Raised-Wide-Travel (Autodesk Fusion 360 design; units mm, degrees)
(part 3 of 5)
sketch "Support-free horizontal rail hole roof" plane through (0, 0, 54.9) normal (0, 0, 1) x axis (1, 0, 0)
  line L1 (-28.0908, -83.0908) -> (-28.0908, -86.9092)
  line L2 (-26.1816, -85) -> (-28.0908, -83.0908)
  line L3 (-28.0908, -86.9092) -> (-26.1816, -85)
extrude "Extrude66" cut sketch "Support-free horizontal rail hole roof" along normal blind 9.2
work_plane "WorkPlane67" AlongDistance 54.9 ExtraOffset 0
sketch "Support-free horizontal rail hole roof (1)" plane through (0, 0, 54.9) normal (0, 0, 1) x axis (1, 0, 0)
  line L1 (-28.0908, 86.9092) -> (-28.0908, 83.0908)
  line L2 (-26.1816, 85) -> (-28.0908, 86.9092)
  line L3 (-28.0908, 83.0908) -> (-26.1816, 85)
extrude "Extrude67" cut sketch "Support-free horizontal rail hole roof (1)" along normal blind 9.2
work_plane "WorkPlane61" AlongDistance 54.9 ExtraOffset 0
sketch "Support-free horizontal rail hole roof" plane through (0, 0, 54.9) normal (0, 0, 1) x axis (1, 0, 0)
  line L1 (31.9092, -83.0908) -> (31.9092, -86.9092)
  line L2 (33.8184, -85) -> (31.9092, -83.0908)
  line L3 (31.9092, -86.9092) -> (33.8184, -85)
extrude "Extrude61" cut sketch "Support-free horizontal rail hole roof" along normal blind 9.2
work_plane "WorkPlane62" AlongDistance 54.9 ExtraOffset 0
sketch "Support-free horizontal rail hole roof (1)" plane through (0, 0, 54.9) normal (0, 0, 1) x axis (1, 0, 0)
  line L1 (31.9092, 86.9092) -> (31.9092, 83.0908)
  line L2 (33.8184, 85) -> (31.9092, 86.9092)
  line L3 (31.9092, 83.0908) -> (33.8184, 85)
extrude "Extrude62" cut sketch "Support-free horizontal rail hole roof (1)" along normal blind 9.2
work_plane "WorkPlane14" AlongDistance 4 ExtraOffset 0
sketch "Reinforced roof over support-free pivot bore" plane through (4, 0, 0) normal (1, 0, 0) x axis (0, 0, -1)
  line L1 (-17.9, -29) -> (-17.9, -41)
  line L2 (-20, -29) -> (-17.9, -29)
  line L3 (-20, -41) -> (-20, -29)
  line L4 (-17.9, -41) -> (-20, -41)
extrude "Extrude14" add sketch "Reinforced roof over support-free pivot bore" along normal blind 3
work_plane "WorkPlane15" AlongDistance 4 ExtraOffset 0
sketch "Flat print foot below roller cheek" plane through (4, 0, 0) normal (1, 0, 0) x axis (0, 0, -1)
  line L1 (-6, 6) -> (-6, -6)
  line L2 (-12, 6) -> (-6, 6)
  line L3 (-12, -6) -> (-12, 6)
  line L4 (-6, -6) -> (-12, -6)
extrude "Extrude15" add sketch "Flat print foot below roller cheek" along normal blind 3
work_plane "WorkPlane16" AlongDistance 17 ExtraOffset 0
sketch "Reinforced roof over support-free pivot bore (1)" plane through (17, 0, 0) normal (1, 0, 0) x axis (0, 0, -1)
  line L1 (-17.9, -29) -> (-17.9, -41)
  line L2 (-20, -29) -> (-17.9, -29)
  line L3 (-20, -41) -> (-20, -29)
  line L4 (-17.9, -41) -> (-20, -41)
extrude "Extrude16" add sketch "Reinforced roof over support-free pivot bore (1)" along normal blind 3
work_plane "WorkPlane17" AlongDistance 17 ExtraOffset 0
sketch "Flat print foot below roller cheek (1)" plane through (17, 0, 0) normal (1, 0, 0) x axis (0, 0, -1)
  line L1 (-6, 6) -> (-6, -6)
  line L2 (-12, 6) -> (-6, 6)
  line L3 (-12, -6) -> (-12, 6)
  line L4 (-6, -6) -> (-12, -6)
extrude "Extrude17" add sketch "Flat print foot below roller cheek (1)" along normal blind 3
work_plane "WorkPlane18" AlongDistance 3.9 ExtraOffset 0
sketch "Follower horizontal bore 45 degree roof" plane through (3.9, 0, 0) normal (1, 0, 0) x axis (0, 0, -1)
  line L1 (-14.9345, -32.0655) -> (-14.9345, -37.9345)
  line L2 (-17.869, -35) -> (-14.9345, -32.0655)
  line L3 (-14.9345, -37.9345) -> (-17.869, -35)
extrude "Extrude18" cut sketch "Follower horizontal bore 45 degree roof" along normal blind 16.2
work_plane "WorkPlane19" AlongDistance 3.9 ExtraOffset 0
sketch "Follower horizontal bore 45 degree roof (1)" plane through (3.9, 0, 0) normal (1, 0, 0) x axis (0, 0, -1)
  line L1 (-13.2021, 1.2021) -> (-13.2021, -1.2021)
  line L2 (-14.4042, 0) -> (-13.2021, 1.2021)
  line L3 (-13.2021, -1.2021) -> (-14.4042, 0)
extrude "Extrude19" cut sketch "Follower horizontal bore 45 degree roof (1)" along normal blind 16.2
work_plane "WorkPlane11" AlongDistance 9 ExtraOffset 0
sketch "Upright grip head pocket roof" plane through (9, 0, 0) normal (1, 0, 0) x axis (0, 0, -1)
  line L1 (-182.192, -2.192) -> (-182.192, 2.192)
  line L2 (-184.3841, 0) -> (-182.192, -2.192)
  line L3 (-182.192, 2.192) -> (-184.3841, 0)
extrude "Extrude10" cut sketch "Upright grip head pocket roof" along normal blind 16
work_plane "WorkPlane12" AlongDistance 9 ExtraOffset 0
sketch "Upright grip head pocket roof (1)" plane through (9, 0, 0) normal (1, 0, 0) x axis (0, 0, -1)
  line L1 (-192.192, -2.192) -> (-192.192, 2.192)
  line L2 (-194.3841, 0) -> (-192.192, -2.192)
  line L3 (-192.192, 2.192) -> (-194.3841, 0)
extrude "Extrude11" cut sketch "Upright grip head pocket roof (1)" along normal blind 16
work_plane "WorkPlane1" AlongDistance -4.5 ExtraOffset 0
sketch "Shaft joining M3x8 -15" plane through (0, -4.5, 0) normal (0, 1, 0) x axis (1, 0, 0)
  circle C1 centre (-15, -65) radius 1.5
extrude "Extrude1" new body sketch "Shaft joining M3x8 -15" along normal blind 8 bodies "HARDWARE Shaft joining M3x8 -15"
work_plane "WorkPlane2" AlongDistance 3.5 ExtraOffset 0
sketch "Button head" plane through (0, 3.5, 0) normal (0, 1, 0) x axis (1, 0, 0)
  circle C1 centre (-15, -65) radius 2.75
extrude "Extrude2" add sketch "Button head" along normal blind 3
work_plane "WorkPlane1" AlongDistance -4.5 ExtraOffset 0
sketch "Shaft joining M3x8 15" plane through (0, -4.5, 0) normal (0, 1, 0) x axis (1, 0, 0)
  circle C1 centre (15, -65) radius 1.5
extrude "Extrude1" new body sketch "Shaft joining M3x8 15" along normal blind 8 bodies "HARDWARE Shaft joining M3x8 15"
work_plane "WorkPlane2" AlongDistance 3.5 ExtraOffset 0
sketch "Button head" plane through (0, 3.5, 0) normal (0, 1, 0) x axis (1, 0, 0)
  circle C1 centre (15, -65) radius 2.75
extrude "Extrude2" add sketch "Button head" along normal blind 3
work_plane "WorkPlane1" AlongDistance -6.5 ExtraOffset 0
sketch "Loose flat printable alignment key" plane through (-6.5, 0, 0) normal (1, 0, 0) x axis (0, 0, -1)
  line L1 (-61.1, 1.5) -> (-61.1, -1.5)
  line L2 (-68.9, 1.5) -> (-61.1, 1.5)
  line L3 (-68.9, -1.5) -> (-68.9, 1.5)
  line L4 (-61.1, -1.5) -> (-68.9, -1.5)
extrude "Extrude1" new body sketch "Loose flat printable alignment key" along normal blind 3 bodies "P28 Shaft alignment key -5"
work_plane "WorkPlane1" AlongDistance 3.5 ExtraOffset 0
sketch "Loose flat printable alignment key" plane through (3.5, 0, 0) normal (1, 0, 0) x axis (0, 0, -1)
  line L1 (-61.1, 1.5) -> (-61.1, -1.5)
  line L2 (-68.9, 1.5) -> (-61.1, 1.5)
  line L3 (-68.9, -1.5) -> (-68.9, 1.5)
  line L4 (-61.1, -1.5) -> (-68.9, -1.5)
extrude "Extrude1" new body sketch "Loose flat printable alignment key" along normal blind 3 bodies "P28 Shaft alignment key 5"
work_plane "WorkPlane19" AlongDistance -5 ExtraOffset 0
sketch "Direct cap-head rotor clamp seat" plane through (-5, 0, 0) normal (1, 0, 0) x axis (0, 0, -1)
  line L1 (-60, 22.5) -> (-60, 22)
  line L2 (-70, 22.5) -> (-60, 22.5)
  line L3 (-70, 22) -> (-70, 22.5)
  line L4 (-60, 22) -> (-70, 22)
extrude "Extrude19" add sketch "Direct cap-head rotor clamp seat" along normal blind 10
work_plane "WorkPlane20" AlongDistance 21.9 ExtraOffset 0
sketch "Restore rotor screw through raised seat" plane through (0, 21.9, 0) normal (0, 1, 0) x axis (1, 0, 0)
  circle C1 centre (0, -65) radius 1.7
extrude "Extrude20" cut sketch "Restore rotor screw through raised seat" along normal blind 0.7
work_plane "WorkPlane1" AlongDistance -39.35 ExtraOffset 0
sketch "Main shaft cap M3x8 cap head" plane through (-39.35, 0, 0) normal (1, 0, 0) x axis (0, 0, -1)
  circle C1 centre (-65, 0) radius 1.5
extrude "Extrude1" new body sketch "Main shaft cap M3x8 cap head" along normal blind 8 bodies "HARDWARE Main shaft cap M3x8 cap head"
work_plane "WorkPlane2" AlongDistance -42.35 ExtraOffset 0
sketch "Button head" plane through (-42.35, 0, 0) normal (1, 0, 0) x axis (0, 0, -1)
  circle C1 centre (-65, 0) radius 2.75
extrude "Extrude2" add sketch "Button head" along normal blind 3
work_plane "WorkPlane1" AlongDistance 2 ExtraOffset 0
sketch "Cam M3x10 cap head -45" plane through (2, 0, 0) normal (1, 0, 0) x axis (0, 0, -1)
  circle C1 centre (-39.5442, 25.4558) radius 1.5
extrude "Extrude1" new body sketch "Cam M3x10 cap head -45" along normal blind 10 bodies "HARDWARE Cam M3x10 cap head -45"
work_plane "WorkPlane2" AlongDistance 12 ExtraOffset 0
sketch "Button head" plane through (12, 0, 0) normal (1, 0, 0) x axis (0, 0, -1)
  circle C1 centre (-39.5442, 25.4558) radius 2.75
extrude "Extrude2" add sketch "Button head" along normal blind 3
work_plane "WorkPlane1" AlongDistance 2 ExtraOffset 0
sketch "Cam M3x10 cap head 0" plane through (2, 0, 0) normal (1, 0, 0) x axis (0, 0, -1)
  circle C1 centre (-29, 0) radius 1.5
extrude "Extrude1" new body sketch "Cam M3x10 cap head 0" along normal blind 10 bodies "HARDWARE Cam M3x10 cap head 0"
work_plane "WorkPlane2" AlongDistance 12 ExtraOffset 0
sketch "Button head" plane through (12, 0, 0) normal (1, 0, 0) x axis (0, 0, -1)
  circle C1 centre (-29, 0) radius 2.75
extrude "Extrude2" add sketch "Button head" along normal blind 3
work_plane "WorkPlane1" AlongDistance 2 ExtraOffset 0
sketch "Cam M3x10 cap head 45" plane through (2, 0, 0) normal (1, 0, 0) x axis (0, 0, -1)
  circle C1 centre (-39.5442, -25.4558) radius 1.5
extrude "Extrude1" new body sketch "Cam M3x10 cap head 45" along normal blind 10 bodies "HARDWARE Cam M3x10 cap head 45"
work_plane "WorkPlane2" AlongDistance 12 ExtraOffset 0
sketch "Button head" plane through (12, 0, 0) normal (1, 0, 0) x axis (0, 0, -1)
  circle C1 centre (-39.5442, -25.4558) radius 2.75
extrude "Extrude2" add sketch "Button head" along normal blind 3
work_plane "WorkPlane1" AlongDistance 0 ExtraOffset 0
sketch "Roller axle M3x20 cap head" plane through (0, 0, 0) normal (1, 0, 0) x axis (0, 0, -1)
  circle C1 centre (-12, 0) radius 1.5
extrude "Extrude1" new body sketch "Roller axle M3x20 cap head" along normal blind 20 bodies "HARDWARE Roller axle M3x20 cap head"
work_plane "WorkPlane2" AlongDistance 20 ExtraOffset 0
sketch "Button head" plane through (20, 0, 0) normal (1, 0, 0) x axis (0, 0, -1)
  circle C1 centre (-12, 0) radius 2.75
extrude "Extrude2" add sketch "Button head" along normal blind 3
work_plane "WorkPlane1" AlongDistance -36 ExtraOffset 0
sketch "Crossblock M3x20 cap head (-62, -1)" plane through (-36, 0, 0) normal (1, 0, 0) x axis (0, 0, -1)
  circle C1 centre (-53.5, -62) radius 1.5
extrude "Extrude1" new body sketch "Crossblock M3x20 cap head (-62, -1)" along normal blind 20 bodies "HARDWARE Crossblock M3x20 cap head (-62, -1)"
work_plane "WorkPlane2" AlongDistance -39 ExtraOffset 0
sketch "Button head" plane through (-39, 0, 0) normal (1, 0, 0) x axis (0, 0, -1)
  circle C1 centre (-53.5, -62) radius 2.75
extrude "Extrude2" add sketch "Button head" along normal blind 3
work_plane "WorkPlane1" AlongDistance 16 ExtraOffset 0
sketch "Crossblock M3x20 cap head (-62, 1)" plane through (16, 0, 0) normal (1, 0, 0) x axis (0, 0, -1)
  circle C1 centre (-53.5, -62) radius 1.5
extrude "Extrude1" new body sketch "Crossblock M3x20 cap head (-62, 1)" along normal blind 20 bodies "HARDWARE Crossblock M3x20 cap head (-62, 1)"
work_plane "WorkPlane2" AlongDistance 36 ExtraOffset 0
sketch "Button head" plane through (36, 0, 0) normal (1, 0, 0) x axis (0, 0, -1)
  circle C1 centre (-53.5, -62) radius 2.75
extrude "Extrude2" add sketch "Button head" along normal blind 3
work_plane "WorkPlane1" AlongDistance -36 ExtraOffset 0
sketch "Crossblock M3x20 cap head (-70, -1)" plane through (-36, 0, 0) normal (1, 0, 0) x axis (0, 0, -1)
  circle C1 centre (-53.5, -70) radius 1.5
extrude "Extrude1" new body sketch "Crossblock M3x20 cap head (-70, -1)" along normal blind 20 bodies "HARDWARE Crossblock M3x20 cap head (-70, -1)"
work_plane "WorkPlane2" AlongDistance -39 ExtraOffset 0
sketch "Button head" plane through (-39, 0, 0) normal (1, 0, 0) x axis (0, 0, -1)
  circle C1 centre (-53.5, -70) radius 2.75
extrude "Extrude2" add sketch "Button head" along normal blind 3
work_plane "WorkPlane1" AlongDistance 16 ExtraOffset 0
sketch "Crossblock M3x20 cap head (-70, 1)" plane through (16, 0, 0) normal (1, 0, 0) x axis (0, 0, -1)
  circle C1 centre (-53.5, -70) radius 1.5
extrude "Extrude1" new body sketch "Crossblock M3x20 cap head (-70, 1)" along normal blind 20 bodies "HARDWARE Crossblock M3x20 cap head (-70, 1)"
work_plane "WorkPlane2" AlongDistance 36 ExtraOffset 0
sketch "Button head" plane through (36, 0, 0) normal (1, 0, 0) x axis (0, 0, -1)
  circle C1 centre (-53.5, -70) radius 2.75
extrude "Extrude2" add sketch "Button head" along normal blind 3
work_plane "WorkPlane1" AlongDistance 6.5 ExtraOffset 0
sketch "Rotor clamp M3x16 cap head" plane through (0, 6.5, 0) normal (0, 1, 0) x axis (1, 0, 0)
  circle C1 centre (0, -65) radius 1.5
extrude "Extrude1" new body sketch "Rotor clamp M3x16 cap head" along normal blind 16 bodies "HARDWARE Rotor clamp M3x16 cap head"
work_plane "WorkPlane2" AlongDistance 22.5 ExtraOffset 0
sketch "Button head" plane through (0, 22.5, 0) normal (0, 1, 0) x axis (1, 0, 0)
  circle C1 centre (0, -65) radius 2.75
extrude "Extrude2" add sketch "Button head" along normal blind 3
work_plane "WorkPlane20" AlongDistance 3.9 ExtraOffset 0
sketch "Restore axle bore after adding print feet" plane through (3.9, 0, 0) normal (1, 0, 0) x axis (0, 0, -1)
  circle C1 centre (-12, 0) radius 1.7
extrude "Extrude20" cut sketch "Restore axle bore after adding print feet" along normal blind 16.2
work_plane "WorkPlane21" AlongDistance 3.9 ExtraOffset 0
sketch "Restore nut installation recess after print foot" plane through (3.9, 0, 0) normal (1, 0, 0) x axis (0, 0, -1)
  line L1 (-14.9, 1.6743) -> (-12, 3.3486)
  line L2 (-14.9, -1.6743) -> (-14.9, 1.6743)
  line L3 (-12, -3.3486) -> (-14.9, -1.6743)
  line L4 (-9.1, -1.6743) -> (-12, -3.3486)
  line L5 (-9.1, 1.6743) -> (-9.1, -1.6743)
  line L6 (-12, 3.3486) -> (-9.1, 1.6743)
extrude "Extrude21" cut sketch "Restore nut installation recess after print foot" along normal blind 1.6
work_plane "WorkPlane3" AlongDistance 8 ExtraOffset 0
sketch "Retain one mm preload travel before head meets collar" plane through (8, 0, 0) normal (1, 0, 0) x axis (0, 0, -1)
  line L1 (-56, -51) -> (-56, -59)
  line L2 (-57.1, -51) -> (-56, -51)
  line L3 (-57.1, -59) -> (-57.1, -51)
  line L4 (-56, -59) -> (-57.1, -59)
extrude "Extrude3" cut sketch "Retain one mm preload travel before head meets collar" along normal blind 8
work_plane "WorkPlane63" AlongDistance 20.8 ExtraOffset 0
sketch "Clear stocked carriage screw tip beyond insert" plane through (0, 20.8, 0) normal (0, 1, 0) x axis (1, 0, 0)
  circle C1 centre (60.15, -65) radius 1.7
extrude "Extrude63" cut sketch "Clear stocked carriage screw tip beyond insert" along normal blind 0.6
work_plane "WorkPlane64" AlongDistance -21.4 ExtraOffset 0
sketch "Clear stocked carriage screw tip beyond insert (1)" plane through (0, -21.4, 0) normal (0, 1, 0) x axis (1, 0, 0)
  circle C1 centre (60.15, -65) radius 1.7
extrude "Extrude64" cut sketch "Clear stocked carriage screw tip beyond insert (1)" along normal blind 0.6
work_plane "WorkPlane22" AlongDistance -2.5 ExtraOffset 0
sketch "Support-free lower ramp under left inner-race pad" plane through (0, -2.5, 0) normal (0, 1, 0) x axis (1, 0, 0)
  line L1 (8.1, -9.5) -> (7, -9.5)
  line L2 (8.1, -10.7) -> (8.1, -9.5)
  line L3 (7, -9.6) -> (8.1, -10.7)
  line L4 (7, -9.5) -> (7, -9.6)
extrude "Extrude22" cut sketch "Support-free lower ramp under left inner-race pad" along normal blind 5
work_plane "WorkPlane23" AlongDistance -2.5 ExtraOffset 0
sketch "Support-free lower ramp under right inner-race pad" plane through (0, -2.5, 0) normal (0, 1, 0) x axis (1, 0, 0)
  line L1 (17, -9.5) -> (15.9, -9.5)
  line L2 (17, -9.6) -> (17, -9.5)
  line L3 (15.9, -10.7) -> (17, -9.6)
  line L4 (15.9, -9.5) -> (15.9, -10.7)
extrude "Extrude23" cut sketch "Support-free lower ramp under right inner-race pad" along normal blind 5
ground "Pin100"
ground "Pin101"
ground "Pin106"
ground "Pin107"
ground "Pin108"
ground "Pin109"
ground "Pin110"
ground "Pin111"
ground "Pin112"
ground "Pin113"
ground "Pin120"
ground "Pin121"
ground "Pin122"
ground "Pin123"
work_plane "WorkPlane65" AlongDistance 36 ExtraOffset 0
sketch "Remove Oldham carriage extensions" plane through (36, 0, 0) normal (1, 0, 0) x axis (0, 0, -1)
  line L1 (-46, 34) -> (-46, -34)
  line L2 (-84, 34) -> (-46, 34)
  line L3 (-84, -34) -> (-84, 34)
  line L4 (-46, -34) -> (-84, -34)
extrude "Extrude65" cut sketch "Remove Oldham carriage extensions" along normal blind 30.3
work_plane "WorkPlane66" AlongDistance 24 ExtraOffset 0
sketch "Upper geared sensor support" plane through (24, 0, 0) normal (1, 0, 0) x axis (0, 0, -1)
  line L1 (-78, -10) -> (-78, -23)
  line L2 (-126, -10) -> (-78, -10)
  line L3 (-126, -23) -> (-126, -10)
  line L4 (-78, -23) -> (-126, -23)
extrude "Extrude66" add sketch "Upper geared sensor support" along normal blind 10
work_plane "WorkPlane67" AlongDistance 24 ExtraOffset 0
sketch "Geared mount M3 insert from inboard face" plane through (24, 0, 0) normal (1, 0, 0) x axis (0, 0, -1)
  circle C1 centre (-110.15, -16) radius 2
extrude "Extrude67" cut sketch "Geared mount M3 insert from inboard face" along normal blind 6.8
work_plane "WorkPlane68" AlongDistance 30.7 ExtraOffset 0
sketch "Geared mount screw clearance" plane through (30.7, 0, 0) normal (1, 0, 0) x axis (0, 0, -1)
  circle C1 centre (-110.15, -16) radius 1.7
extrude "Extrude68" cut sketch "Geared mount screw clearance" along normal blind 3.4
work_plane "WorkPlane69" AlongDistance 24 ExtraOffset 0
sketch "Upper geared sensor support (1)" plane through (24, 0, 0) normal (1, 0, 0) x axis (0, 0, -1)
  line L1 (-78, 23) -> (-78, 10)
  line L2 (-126, 23) -> (-78, 23)
  line L3 (-126, 10) -> (-126, 23)
  line L4 (-78, 10) -> (-126, 10)
extrude "Extrude69" add sketch "Upper geared sensor support (1)" along normal blind 10
work_plane "WorkPlane70" AlongDistance 24 ExtraOffset 0
sketch "Geared mount M3 insert from inboard face (1)" plane through (24, 0, 0) normal (1, 0, 0) x axis (0, 0, -1)
  circle C1 centre (-110.15, 16) radius 2
extrude "Extrude70" cut sketch "Geared mount M3 insert from inboard face (1)" along normal blind 6.8
work_plane "WorkPlane71" AlongDistance 30.7 ExtraOffset 0
sketch "Geared mount screw clearance (1)" plane through (30.7, 0, 0) normal (1, 0, 0) x axis (0, 0, -1)
  circle C1 centre (-110.15, 16) radius 1.7
extrude "Extrude71" cut sketch "Geared mount screw clearance (1)" along normal blind 3.4
work_plane "WorkPlane1" AlongDistance -37.35 ExtraOffset 0
sketch "Continuous 12 mm journals" plane through (-37.35, 0, 0) normal (1, 0, 0) x axis (0, 0, -1)
  circle C1 centre (-65, 0) radius 6
extrude "Extrude1" new body sketch "Continuous 12 mm journals" along normal blind 74.7 bodies "P05G Shaft lower half"
work_plane "WorkPlane2" AlongDistance -23.8 ExtraOffset 0
sketch "Structural shaft" plane through (-23.8, 0, 0) normal (1, 0, 0) x axis (0, 0, -1)
  circle C1 centre (-65, 0) radius 8
extrude "Extrude2" add sketch "Structural shaft" along normal blind 47.6
work_plane "WorkPlane3" AlongDistance -23.9 ExtraOffset 0
sketch "Rotor D flat" plane through (-23.9, 0, 0) normal (1, 0, 0) x axis (0, 0, -1)
  line L1 (-56, 9) -> (-56, 6.5)
  line L2 (-74, 9) -> (-56, 9)
  line L3 (-74, 6.5) -> (-74, 9)
  line L4 (-56, 6.5) -> (-74, 6.5)
extrude "Extrude3" cut sketch "Rotor D flat" along normal blind 47.8
work_plane "WorkPlane4" AlongDistance 37.35 ExtraOffset 0
sketch "Retain axial shoulder" plane through (37.35, 0, 0) normal (1, 0, 0) x axis (0, 0, -1)
  circle C1 centre (-65, 0) radius 10
extrude "Extrude4" add sketch "Retain axial shoulder" along normal blind 3
work_plane "WorkPlane5" AlongDistance 40.35 ExtraOffset 0
sketch "Short D drive stub" plane through (40.35, 0, 0) normal (1, 0, 0) x axis (0, 0, -1)
  circle C1 centre (-65, 0) radius 4
extrude "Extrude5" add sketch "Short D drive stub" along normal blind 8
work_plane "WorkPlane6" AlongDistance 40.35 ExtraOffset 0
sketch "Drive stub D flat" plane through (40.35, 0, 0) normal (1, 0, 0) x axis (0, 0, -1)
  line L1 (-60, 5) -> (-60, 3.2)
  line L2 (-70, 5) -> (-60, 5)
  line L3 (-70, 3.2) -> (-70, 5)
  line L4 (-60, 3.2) -> (-70, 3.2)
extrude "Extrude6" cut sketch "Drive stub D flat" along normal blind 8.15
work_plane "WorkPlane7" AlongDistance -37.45 ExtraOffset 0
sketch "End retention insert" plane through (-37.45, 0, 0) normal (1, 0, 0) x axis (0, 0, -1)
  circle C1 centre (-65, 0) radius 2
extrude "Extrude7" cut sketch "End retention insert" along normal blind 6.8
work_plane "WorkPlane8" AlongDistance -6.8 ExtraOffset 0
sketch "Joining insert" plane through (0, -6.8, 0) normal (0, 1, 0) x axis (1, 0, 0)
  circle C1 centre (-15, -65) radius 2
extrude "Extrude8" cut sketch "Joining insert" along normal blind 6.9
work_plane "WorkPlane9" AlongDistance -0.1 ExtraOffset 0
sketch "Joining screw clearance" plane through (0, -0.1, 0) normal (0, 1, 0) x axis (1, 0, 0)
  circle C1 centre (-15, -65) radius 1.7
extrude "Extrude9" cut sketch "Joining screw clearance" along normal blind 6.7
work_plane "WorkPlane10" AlongDistance 3.5 ExtraOffset 0
sketch "Recessed cap head" plane through (0, 3.5, 0) normal (0, 1, 0) x axis (1, 0, 0)
  circle C1 centre (-15, -65) radius 3.1
extrude "Extrude10" cut sketch "Recessed cap head" along normal blind 3.1
work_plane "WorkPlane11" AlongDistance -6.8 ExtraOffset 0
sketch "Joining insert (1)" plane through (0, -6.8, 0) normal (0, 1, 0) x axis (1, 0, 0)
  circle C1 centre (15, -65) radius 2
extrude "Extrude11" cut sketch "Joining insert (1)" along normal blind 6.9
work_plane "WorkPlane12" AlongDistance -0.1 ExtraOffset 0
sketch "Joining screw clearance (1)" plane through (0, -0.1, 0) normal (0, 1, 0) x axis (1, 0, 0)
  circle C1 centre (15, -65) radius 1.7
extrude "Extrude12" cut sketch "Joining screw clearance (1)" along normal blind 6.7
work_plane "WorkPlane13" AlongDistance 3.5 ExtraOffset 0
sketch "Recessed cap head (1)" plane through (0, 3.5, 0) normal (0, 1, 0) x axis (1, 0, 0)
  circle C1 centre (15, -65) radius 3.1
extrude "Extrude13" cut sketch "Recessed cap head (1)" along normal blind 3.1
work_plane "WorkPlane14" AlongDistance -6.6 ExtraOffset 0
sketch "Retain alignment key pocket" plane through (-6.6, 0, 0) normal (1, 0, 0) x axis (0, 0, -1)
  line L1 (-61, 1.6) -> (-61, -1.6)
  line L2 (-69, 1.6) -> (-61, 1.6)
  line L3 (-69, -1.6) -> (-69, 1.6)
  line L4 (-61, -1.6) -> (-69, -1.6)
extrude "Extrude14" cut sketch "Retain alignment key pocket" along normal blind 3.2
work_plane "WorkPlane15" AlongDistance 3.4 ExtraOffset 0
sketch "Retain alignment key pocket (1)" plane through (3.4, 0, 0) normal (1, 0, 0) x axis (0, 0, -1)
  line L1 (-61, 1.6) -> (-61, -1.6)
  line L2 (-69, 1.6) -> (-61, 1.6)
  line L3 (-69, -1.6) -> (-69, 1.6)
  line L4 (-61, -1.6) -> (-69, -1.6)
extrude "Extrude15" cut sketch "Retain alignment key pocket (1)" along normal blind 3.2
split "Split1" bodies "P05G Shaft upper half"
work_plane "WorkPlane1" AlongDistance 40.5 ExtraOffset 0
sketch "Involute gear polygon m1.25 pressure20" plane through (40.5, 0, 0) normal (1, 0, 0) x axis (0, 0, -1)
  line L1 (-63.7058, 28.408) -> (-63.7058, 28.408)
  line L2 (-63.7507, 28.7619) -> (-63.7058, 28.408)
  line L3 (-63.8186, 29.1167) -> (-63.7507, 28.7619)
  line L4 (-63.9051, 29.4719) -> (-63.8186, 29.1167)
  line L5 (-64.0079, 29.8273) -> (-63.9051, 29.4719)
  line L6 (-64.1255, 30.1826) -> (-64.0079, 29.8273)
  line L7 (-64.257, 30.5378) -> (-64.1255, 30.1826)
  line L8 (-64.4015, 30.8926) -> (-64.257, 30.5378)
  line L9 (-64.5586, 31.2469) -> (-64.4015, 30.8926)
  line L10 (-65.4414, 31.2469) -> (-64.5586, 31.2469)
  line L11 (-65.5985, 30.8926) -> (-65.4414, 31.2469)
  line L12 (-65.743, 30.5378) -> (-65.5985, 30.8926)
  line L13 (-65.8745, 30.1826) -> (-65.743, 30.5378)
  line L14 (-65.9921, 29.8273) -> (-65.8745, 30.1826)
  line L15 (-66.0949, 29.4719) -> (-65.9921, 29.8273)
  line L16 (-66.1814, 29.1167) -> (-66.0949, 29.4719)
  line L17 (-66.2493, 28.7619) -> (-66.1814, 29.1167)
  line L18 (-66.2942, 28.408) -> (-66.2493, 28.7619)
  line L19 (-66.2942, 28.408) -> (-66.2942, 28.408)
  line L20 (-66.5771, 28.3937) -> (-66.2942, 28.408)
  line L21 (-66.8599, 28.3766) -> (-66.5771, 28.3937)
  line L22 (-67.1425, 28.3567) -> (-66.8599, 28.3766)
  line L23 (-67.4248, 28.3339) -> (-67.1425, 28.3567)
  line L24 (-67.4248, 28.3339) -> (-67.4248, 28.3339)
  line L25 (-67.5156, 28.6789) -> (-67.4248, 28.3339)
  line L26 (-67.6292, 29.0218) -> (-67.5156, 28.6789)
  line L27 (-67.7613, 29.3626) -> (-67.6292, 29.0218)
  line L28 (-67.9096, 29.7016) -> (-67.7613, 29.3626)
  line L29 (-68.0726, 30.0386) -> (-67.9096, 29.7016)
  line L30 (-68.2493, 30.3736) -> (-68.0726, 30.0386)
  line L31 (-68.4389, 30.7065) -> (-68.2493, 30.3736)
  line L32 (-68.6409, 31.0372) -> (-68.4389, 30.7065)
  line L33 (-69.5162, 30.9219) -> (-68.6409, 31.0372)
  line L34 (-69.6257, 30.5502) -> (-69.5162, 30.9219)
  line L35 (-69.7227, 30.1796) -> (-69.6257, 30.5502)
  line L36 (-69.8066, 29.8103) -> (-69.7227, 30.1796)
  line L37 (-69.8769, 29.4426) -> (-69.8066, 29.8103)
  line L38 (-69.9324, 29.0768) -> (-69.8769, 29.4426)
  line L39 (-69.9718, 28.7134) -> (-69.9324, 29.0768)
  line L40 (-69.9928, 28.3528) -> (-69.9718, 28.7134)
  line L41 (-69.9911, 27.9961) -> (-69.9928, 28.3528)
  line L42 (-69.9911, 27.9961) -> (-69.9911, 27.9961)
  line L43 (-70.2698, 27.945) -> (-69.9911, 27.9961)
  line L44 (-70.5479, 27.8911) -> (-70.2698, 27.945)
  line L45 (-70.8254, 27.8344) -> (-70.5479, 27.8911)
  line L46 (-71.1024, 27.775) -> (-70.8254, 27.8344)
  line L47 (-71.1024, 27.775) -> (-71.1024, 27.775)
  line L48 (-71.2374, 28.1052) -> (-71.1024, 27.775)
  line L49 (-71.3948, 28.4303) -> (-71.2374, 28.1052)
  line L50 (-71.5703, 28.751) -> (-71.3948, 28.4303)
  line L51 (-71.7616, 29.0677) -> (-71.5703, 28.751)
  line L52 (-71.9672, 29.3805) -> (-71.7616, 29.0677)
  line L53 (-72.1861, 29.6896) -> (-71.9672, 29.3805)
  line L54 (-72.4175, 29.9949) -> (-72.1861, 29.6896)
  line L55 (-72.6609, 30.2964) -> (-72.4175, 29.9949)
  line L56 (-73.5136, 30.0679) -> (-72.6609, 30.2964)
  line L57 (-73.5737, 29.6851) -> (-73.5136, 30.0679)
  line L58 (-73.6215, 29.305) -> (-73.5737, 29.6851)
  line L59 (-73.6565, 28.9279) -> (-73.6215, 29.305)
  line L60 (-73.6782, 28.5541) -> (-73.6565, 28.9279)
  line L61 (-73.6854, 28.1843) -> (-73.6782, 28.5541)
  line L62 (-73.6771, 27.8188) -> (-73.6854, 28.1843)
  line L63 (-73.6509, 27.4586) -> (-73.6771, 27.8188)
  line L64 (-73.6027, 27.1051) -> (-73.6509, 27.4586)
  line L65 (-73.6027, 27.1051) -> (-73.6027, 27.1051)
  line L66 (-73.8722, 27.018) -> (-73.6027, 27.1051)
  line L67 (-74.1409, 26.9283) -> (-73.8722, 27.018)
  line L68 (-74.4087, 26.8359) -> (-74.1409, 26.9283)
  line L69 (-74.6756, 26.7409) -> (-74.4087, 26.8359)
  line L70 (-74.6756, 26.7409) -> (-74.6756, 26.7409)
  line L71 (-74.8525, 27.0507) -> (-74.6756, 26.7409)
  line L72 (-75.051, 27.3524) -> (-74.8525, 27.0507)
  line L73 (-75.2669, 27.6474) -> (-75.051, 27.3524)
  line L74 (-75.4978, 27.9365) -> (-75.2669, 27.6474)
  line L75 (-75.7425, 28.2198) -> (-75.4978, 27.9365)
  line L76 (-75.9999, 28.4976) -> (-75.7425, 28.2198)
  line L77 (-76.2692, 28.7701) -> (-75.9999, 28.4976)
  line L78 (-76.5499, 29.0373) -> (-76.2692, 28.7701)
  line L79 (-77.3655, 28.6994) -> (-76.5499, 29.0373)
  line L80 (-77.375, 28.3121) -> (-77.3655, 28.6994)
  line L81 (-77.3728, 27.9289) -> (-77.375, 28.3121)
  line L82 (-77.3583, 27.5505) -> (-77.3728, 27.9289)
  line L83 (-77.331, 27.1771) -> (-77.3583, 27.5505)
  line L84 (-77.2899, 26.8095) -> (-77.331, 27.1771)
  line L85 (-77.2339, 26.4482) -> (-77.2899, 26.8095)
  line L86 (-77.1609, 26.0945) -> (-77.2339, 26.4482)
  line L87 (-77.067, 25.7503) -> (-77.1609, 26.0945)
  line L88 (-77.067, 25.7503) -> (-77.067, 25.7503)
  line L89 (-77.3229, 25.6288) -> (-77.067, 25.7503)
  line L90 (-77.5776, 25.5048) -> (-77.3229, 25.6288)
  line L91 (-77.831, 25.3783) -> (-77.5776, 25.5048)
  line L92 (-78.0832, 25.2492) -> (-77.831, 25.3783)
  line L93 (-78.0832, 25.2492) -> (-78.0832, 25.2492)
  line L94 (-78.299, 25.5332) -> (-78.0832, 25.2492)
  line L95 (-78.5352, 25.8065) -> (-78.299, 25.5332)
  line L96 (-78.7877, 26.0708) -> (-78.5352, 25.8065)
  line L97 (-79.0544, 26.3272) -> (-78.7877, 26.0708)
  line L98 (-79.334, 26.5762) -> (-79.0544, 26.3272)
  line L99 (-79.6254, 26.8181) -> (-79.334, 26.5762)
  line L100 (-79.928, 27.0531) -> (-79.6254, 26.8181)
  line L101 (-80.2412, 27.2813) -> (-79.928, 27.0531)
  line L102 (-81.0057, 26.8399) -> (-80.2412, 27.2813)
  line L103 (-80.9646, 26.4546) -> (-81.0057, 26.8399)
  line L104 (-80.9124, 26.075) -> (-80.9646, 26.4546)
  line L105 (-80.8487, 25.7017) -> (-80.9124, 26.075)
  line L106 (-80.7728, 25.3351) -> (-80.8487, 25.7017)
  line L107 (-80.6841, 24.9759) -> (-80.7728, 25.3351)
  line L108 (-80.5814, 24.6251) -> (-80.6841, 24.9759)
  line L109 (-80.4629, 24.2839) -> (-80.5814, 24.6251)
  line L110 (-80.3249, 23.955) -> (-80.4629, 24.2839)
  line L111 (-80.3249, 23.955) -> (-80.3249, 23.955)
  line L112 (-80.5627, 23.8011) -> (-80.3249, 23.955)
  line L113 (-80.799, 23.6449) -> (-80.5627, 23.8011)
  line L114 (-81.0338, 23.4864) -> (-80.799, 23.6449)
  line L115 (-81.2669, 23.3255) -> (-81.0338, 23.4864)
  line L116 (-81.2669, 23.3255) -> (-81.2669, 23.3255)
  line L117 (-81.518, 23.5789) -> (-81.2669, 23.3255)
  line L118 (-81.7879, 23.819) -> (-81.518, 23.5789)
  line L119 (-82.0727, 24.0481) -> (-81.7879, 23.819)
  line L120 (-82.3706, 24.2675) -> (-82.0727, 24.0481)
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extrude "Extrude1" new body sketch "Involute gear polygon m1.25 pressure20" along normal blind 8 bodies "G01R 48T gear with upper clamp"
work_plane "WorkPlane2" AlongDistance 40.4 ExtraOffset 0
sketch "Shaft bore" plane through (40.4, 0, 0) normal (1, 0, 0) x axis (0, 0, -1)
  circle C1 centre (-65, 0) radius 4.1
extrude "Extrude2" cut sketch "Shaft bore" along normal blind 8.2
work_plane "WorkPlane3" AlongDistance 40.5 ExtraOffset 0
sketch "D key flat" plane through (40.5, 0, 0) normal (1, 0, 0) x axis (0, 0, -1)
  line L1 (-62, 4.3) -> (-62, 3.35)
  line L2 (-68, 4.3) -> (-62, 4.3)
  line L3 (-68, 3.35) -> (-68, 4.3)
  line L4 (-62, 3.35) -> (-68, 3.35)
extrude "Extrude3" add sketch "D key flat" along normal blind 8
work_plane "WorkPlane4" AlongDistance 40.4 ExtraOffset 0
sketch "Clamp slit outside operating mesh sector" plane through (40.4, 0, 0) normal (1, 0, 0) x axis (0, 0, -1)
  line L1 (-32, 0.2) -> (-32, -0.2)
  line L2 (-65, 0.2) -> (-32, 0.2)
  line L3 (-65, -0.2) -> (-65, 0.2)
  line L4 (-32, -0.2) -> (-65, -0.2)
work_plane "WorkPlane5" AlongDistance -8 ExtraOffset 0
sketch "Clamp heat-set insert pocket" plane through (0, -8, 0) normal (0, 1, 0) x axis (1, 0, 0)
  circle C1 centre (44.5, -57) radius 2
work_plane "WorkPlane6" AlongDistance -1.3 ExtraOffset 0
sketch "Clamp through screw" plane through (0, -1.3, 0) normal (0, 1, 0) x axis (1, 0, 0)
  circle C1 centre (44.5, -57) radius 1.7
work_plane "WorkPlane7" AlongDistance 5 ExtraOffset 0
sketch "Recessed clamp screw head and tool path" plane through (0, 5, 0) normal (0, 1, 0) x axis (1, 0, 0)
  circle C1 centre (44.5, -57) radius 3.1
work_plane "WorkPlane1" AlongDistance 40.5 ExtraOffset 0
sketch "Involute gear polygon m1.25 pressure20" plane through (40.5, 0, 0) normal (1, 0, 0) x axis (0, 0, -1)
  line L1 (-110.8997, 14.0754) -> (-110.8647, 13.4185)
  line L2 (-110.9494, 14.3425) -> (-110.8997, 14.0754)
  line L3 (-111.0295, 14.6076) -> (-110.9494, 14.3425)
  line L4 (-111.1304, 14.8711) -> (-111.0295, 14.6076)
  line L5 (-111.2488, 15.1329) -> (-111.1304, 14.8711)
  line L6 (-111.383, 15.3927) -> (-111.2488, 15.1329)
  line L7 (-111.5317, 15.6505) -> (-111.383, 15.3927)
  line L8 (-111.6943, 15.9059) -> (-111.5317, 15.6505)
  line L9 (-111.87, 16.1587) -> (-111.6943, 15.9059)
  line L10 (-112.6708, 16.0533) -> (-111.87, 16.1587)
  line L11 (-112.7751, 15.7636) -> (-112.6708, 16.0533)
  line L12 (-112.866, 15.4748) -> (-112.7751, 15.7636)
  line L13 (-112.943, 15.1873) -> (-112.866, 15.4748)
  line L14 (-113.0053, 14.9016) -> (-112.943, 15.1873)
  line L15 (-113.0519, 14.6181) -> (-113.0053, 14.9016)
  line L16 (-113.0812, 14.3375) -> (-113.0519, 14.6181)
  line L17 (-113.0899, 14.0607) -> (-113.0812, 14.3375)
  line L18 (-113.0688, 13.7899) -> (-113.0899, 14.0607)
  line L19 (-112.9326, 13.1462) -> (-113.0688, 13.7899)
  line L20 (-113.2814, 13.0676) -> (-112.9326, 13.1462)
  line L21 (-113.6279, 12.9796) -> (-113.2814, 13.0676)
  line L22 (-113.9719, 12.8825) -> (-113.6279, 12.9796)
  line L23 (-114.3133, 12.7763) -> (-113.9719, 12.8825)
  line L24 (-114.5171, 13.4018) -> (-114.3133, 12.7763)
  line L25 (-114.6343, 13.6468) -> (-114.5171, 13.4018)
  line L26 (-114.7803, 13.8822) -> (-114.6343, 13.6468)
  line L27 (-114.9459, 14.1106) -> (-114.7803, 13.8822)
  line L28 (-115.128, 14.3328) -> (-114.9459, 14.1106)
  line L29 (-115.3249, 14.5491) -> (-115.128, 14.3328)
  line L30 (-115.5353, 14.7596) -> (-115.3249, 14.5491)
  line L31 (-115.7584, 14.9642) -> (-115.5353, 14.7596)
  line L32 (-115.9936, 15.1629) -> (-115.7584, 14.9642)
  line L33 (-116.7398, 14.8539) -> (-115.9936, 15.1629)
  line L34 (-116.7656, 14.547) -> (-116.7398, 14.8539)
  line L35 (-116.7786, 14.2446) -> (-116.7656, 14.547)
  line L36 (-116.7786, 13.947) -> (-116.7786, 14.2446)
  line L37 (-116.7649, 13.6548) -> (-116.7786, 13.947)
  line L38 (-116.7365, 13.3689) -> (-116.7649, 13.6548)
  line L39 (-116.6921, 13.0903) -> (-116.7365, 13.3689)
  line L40 (-116.6289, 12.8206) -> (-116.6921, 13.0903)
  line L41 (-116.5385, 12.5645) -> (-116.6289, 12.8206)
  line L42 (-116.2403, 11.9781) -> (-116.5385, 12.5645)
  line L43 (-116.5568, 11.8118) -> (-116.2403, 11.9781)
  line L44 (-116.8688, 11.6372) -> (-116.5568, 11.8118)
  line L45 (-117.176, 11.4544) -> (-116.8688, 11.6372)
  line L46 (-117.4782, 11.2634) -> (-117.176, 11.4544)
  line L47 (-117.837, 11.8148) -> (-117.4782, 11.2634)
  line L48 (-118.0136, 12.0212) -> (-117.837, 11.8148)
  line L49 (-118.2155, 12.2108) -> (-118.0136, 12.0212)
  line L50 (-118.4346, 12.3885) -> (-118.2155, 12.2108)
  line L51 (-118.668, 12.556) -> (-118.4346, 12.3885)
  line L52 (-118.9141, 12.714) -> (-118.668, 12.556)
  line L53 (-119.1718, 12.8628) -> (-118.9141, 12.714)
  line L54 (-119.4403, 13.0028) -> (-119.1718, 12.8628)
  line L55 (-119.7189, 13.1339) -> (-119.4403, 13.0028)
  line L56 (-120.3597, 12.6422) -> (-119.7189, 13.1339)
  line L57 (-120.3052, 12.3391) -> (-120.3597, 12.6422)
  line L58 (-120.2395, 12.0436) -> (-120.3052, 12.3391)
  line L59 (-120.1625, 11.7561) -> (-120.2395, 12.0436)
  line L60 (-120.0736, 11.4775) -> (-120.1625, 11.7561)
  line L61 (-119.9722, 11.2087) -> (-120.0736, 11.4775)
  line L62 (-119.8572, 10.951) -> (-119.9722, 11.2087)
  line L63 (-119.7264, 10.7069) -> (-119.8572, 10.951)
  line L64 (-119.5727, 10.4829) -> (-119.7264, 10.7069)
  line L65 (-119.1329, 9.9937) -> (-119.5727, 10.4829)
  line L66 (-119.3956, 9.7512) -> (-119.1329, 9.9937)
  line L67 (-119.6517, 9.5017) -> (-119.3956, 9.7512)
  line L68 (-119.9012, 9.2456) -> (-119.6517, 9.5017)
  line L69 (-120.1437, 8.9829) -> (-119.9012, 9.2456)
  line L70 (-120.6329, 9.4227) -> (-120.1437, 8.9829)
  line L71 (-120.8569, 9.5764) -> (-120.6329, 9.4227)
  line L72 (-121.101, 9.7072) -> (-120.8569, 9.5764)
  line L73 (-121.3587, 9.8222) -> (-121.101, 9.7072)
  line L74 (-121.6275, 9.9236) -> (-121.3587, 9.8222)
  line L75 (-121.9061, 10.0125) -> (-121.6275, 9.9236)
  line L76 (-122.1936, 10.0895) -> (-121.9061, 10.0125)
  line L77 (-122.4891, 10.1552) -> (-122.1936, 10.0895)
  line L78 (-122.7922, 10.2097) -> (-122.4891, 10.1552)
  line L79 (-123.2839, 9.5689) -> (-122.7922, 10.2097)
  line L80 (-123.1528, 9.2903) -> (-123.2839, 9.5689)
  line L81 (-123.0128, 9.0218) -> (-123.1528, 9.2903)
  line L82 (-122.864, 8.7641) -> (-123.0128, 9.0218)
  line L83 (-122.706, 8.518) -> (-122.864, 8.7641)
  line L84 (-122.5385, 8.2846) -> (-122.706, 8.518)
  line L85 (-122.3608, 8.0655) -> (-122.5385, 8.2846)
  line L86 (-122.1712, 7.8636) -> (-122.3608, 8.0655)
  line L87 (-121.9648, 7.687) -> (-122.1712, 7.8636)
  line L88 (-121.4134, 7.3282) -> (-121.9648, 7.687)
  line L89 (-121.6044, 7.026) -> (-121.4134, 7.3282)
  line L90 (-121.7872, 6.7187) -> (-121.6044, 7.026)
  line L91 (-121.9618, 6.4068) -> (-121.7872, 6.7187)
  line L92 (-122.1281, 6.0903) -> (-121.9618, 6.4068)
  line L93 (-122.7145, 6.3885) -> (-122.1281, 6.0903)
  line L94 (-122.9706, 6.4789) -> (-122.7145, 6.3885)
  line L95 (-123.2403, 6.5421) -> (-122.9706, 6.4789)
  line L96 (-123.5189, 6.5865) -> (-123.2403, 6.5421)
  line L97 (-123.8048, 6.6149) -> (-123.5189, 6.5865)
  line L98 (-124.097, 6.6286) -> (-123.8048, 6.6149)
  line L99 (-124.3946, 6.6286) -> (-124.097, 6.6286)
  line L100 (-124.697, 6.6156) -> (-124.3946, 6.6286)
  line L101 (-125.0039, 6.5898) -> (-124.697, 6.6156)
  line L102 (-125.3129, 5.8436) -> (-125.0039, 6.5898)
  line L103 (-125.1142, 5.6084) -> (-125.3129, 5.8436)
  line L104 (-124.9096, 5.3853) -> (-125.1142, 5.6084)
  line L105 (-124.6991, 5.1749) -> (-124.9096, 5.3853)
  line L106 (-124.4828, 4.978) -> (-124.6991, 5.1749)
  line L107 (-124.2606, 4.7959) -> (-124.4828, 4.978)
  line L108 (-124.0322, 4.6303) -> (-124.2606, 4.7959)
  line L109 (-123.7968, 4.4843) -> (-124.0322, 4.6303)
  line L110 (-123.5518, 4.3671) -> (-123.7968, 4.4843)
  line L111 (-122.9263, 4.1633) -> (-123.5518, 4.3671)
  line L112 (-123.0325, 3.8219) -> (-122.9263, 4.1633)
  line L113 (-123.1296, 3.4779) -> (-123.0325, 3.8219)
  line L114 (-123.2176, 3.1314) -> (-123.1296, 3.4779)
  line L115 (-123.2962, 2.7826) -> (-123.2176, 3.1314)
  line L116 (-123.9399, 2.9188) -> (-123.2962, 2.7826)
  line L117 (-124.2107, 2.9399) -> (-123.9399, 2.9188)
  line L118 (-124.4875, 2.9312) -> (-124.2107, 2.9399)
  line L119 (-124.7681, 2.9019) -> (-124.4875, 2.9312)
  line L120 (-125.0516, 2.8553) -> (-124.7681, 2.9019)
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extrude "Extrude1" new body sketch "Involute gear polygon m1.25 pressure20" along normal blind 8 bodies "G02 24T sensor pinion"
work_plane "WorkPlane2" AlongDistance 40.4 ExtraOffset 0
sketch "Shaft bore" plane through (40.4, 0, 0) normal (1, 0, 0) x axis (0, 0, -1)
  circle C1 centre (-110.15, 0) radius 3.1
extrude "Extrude2" cut sketch "Shaft bore" along normal blind 8.2
work_plane "WorkPlane3" AlongDistance 40.4 ExtraOffset 0
sketch "Sensor bushing end relief" plane through (40.4, 0, 0) normal (1, 0, 0) x axis (0, 0, -1)
  circle C1 centre (-110.15, 0) radius 3.6
extrude "Extrude3" cut sketch "Sensor bushing end relief" along normal blind 0.9
work_plane "WorkPlane4" AlongDistance 40.4 ExtraOffset 0
sketch "Clamp slit outside operating mesh sector" plane through (40.4, 0, 0) normal (1, 0, 0) x axis (0, 0, -1)
  line L1 (-110.15, 0.2) -> (-110.15, -0.2)
  line L2 (-127, 0.2) -> (-110.15, 0.2)
  line L3 (-127, -0.2) -> (-127, 0.2)
  line L4 (-110.15, -0.2) -> (-127, -0.2)
extrude "Extrude4" cut sketch "Clamp slit outside operating mesh sector" along normal blind 8.2
work_plane "WorkPlane5" AlongDistance -8 ExtraOffset 0
sketch "Clamp heat-set insert pocket" plane through (0, -8, 0) normal (0, 1, 0) x axis (1, 0, 0)
  circle C1 centre (44.5, -118.15) radius 2
work_plane "WorkPlane6" AlongDistance -1.3 ExtraOffset 0
sketch "Clamp through screw" plane through (0, -1.3, 0) normal (0, 1, 0) x axis (1, 0, 0)
  circle C1 centre (44.5, -118.15) radius 1.7
work_plane "WorkPlane7" AlongDistance 5 ExtraOffset 0
sketch "Recessed clamp screw head and tool path" plane through (0, 5, 0) normal (0, 1, 0) x axis (1, 0, 0)
  circle C1 centre (44.5, -118.15) radius 3.1
work_plane "WorkPlane1" AlongDistance 37 ExtraOffset 0
sketch "Geared RK097 supplied washer ASSUMED" plane through (37, 0, 0) normal (1, 0, 0) x axis (0, 0, -1)
  circle C1 centre (-110.15, 0) radius 6
extrude "Extrude1" new body sketch "Geared RK097 supplied washer ASSUMED" along normal blind 0.5 bodies "HARDWARE Geared RK097 supplied washer ASSUMED"
work_plane "WorkPlane2" AlongDistance 36.9 ExtraOffset 0
sketch "Washer clearance" plane through (36.9, 0, 0) normal (1, 0, 0) x axis (0, 0, -1)
  circle C1 centre (-110.15, 0) radius 3.6
extrude "Extrude2" cut sketch "Washer clearance" along normal blind 0.7
work_plane "WorkPlane1" AlongDistance 37.5 ExtraOffset 0
sketch "Geared RK097 supplied nut ASSUMED" plane through (37.5, 0, 0) normal (1, 0, 0) x axis (0, 0, -1)
  line L1 (-115.65, 3.1754) -> (-110.15, 6.3509)
  line L2 (-115.65, -3.1754) -> (-115.65, 3.1754)
  line L3 (-110.15, -6.3509) -> (-115.65, -3.1754)
  line L4 (-104.65, -3.1754) -> (-110.15, -6.3509)
  line L5 (-104.65, 3.1754) -> (-104.65, -3.1754)
  line L6 (-110.15, 6.3509) -> (-104.65, 3.1754)
extrude "Extrude1" new body sketch "Geared RK097 supplied nut ASSUMED" along normal blind 2 bodies "HARDWARE Geared RK097 supplied nut ASSUMED"
work_plane "WorkPlane2" AlongDistance 37.4 ExtraOffset 0
sketch "Thread envelope" plane through (37.4, 0, 0) normal (1, 0, 0) x axis (0, 0, -1)
  circle C1 centre (-110.15, 0) radius 3.5
extrude "Extrude2" cut sketch "Thread envelope" along normal blind 2.2
work_plane "WorkPlane8" AlongDistance -7 ExtraOffset 0
sketch "Revised clamp insert pocket" plane through (0, -7, 0) normal (0, 1, 0) x axis (1, 0, 0)
  circle C1 centre (44.5, -117.65) radius 2
extrude "Extrude8" cut sketch "Revised clamp insert pocket" along normal blind 6.8
work_plane "WorkPlane9" AlongDistance -0.3 ExtraOffset 0
sketch "Revised clamp screw clearance" plane through (0, -0.3, 0) normal (0, 1, 0) x axis (1, 0, 0)
  circle C1 centre (44.5, -117.65) radius 1.7
extrude "Extrude9" cut sketch "Revised clamp screw clearance" along normal blind 5.4
work_plane "WorkPlane10" AlongDistance 5 ExtraOffset 0
sketch "Revised recessed clamp head" plane through (0, 5, 0) normal (0, 1, 0) x axis (1, 0, 0)
  circle C1 centre (44.5, -117.65) radius 3.1
extrude "Extrude10" cut sketch "Revised recessed clamp head" along normal blind 30
work_plane "WorkPlane1" AlongDistance -7 ExtraOffset 0
sketch "G02 24T sensor pinion clamp M3x12" plane through (0, -7, 0) normal (0, 1, 0) x axis (1, 0, 0)
  circle C1 centre (44.5, -117.65) radius 1.5
extrude "Extrude1" new body sketch "G02 24T sensor pinion clamp M3x12" along normal blind 12 bodies "HARDWARE G02 24T sensor pinion clamp M3x12"
work_plane "WorkPlane2" AlongDistance 5 ExtraOffset 0
sketch "Button head" plane through (0, 5, 0) normal (0, 1, 0) x axis (1, 0, 0)
  circle C1 centre (44.5, -117.65) radius 2.75
extrude "Extrude2" add sketch "Button head" along normal blind 3
work_plane "WorkPlane11" AlongDistance 40.4 ExtraOffset 0
sketch "Open support-free clamp tool channel" plane through (40.4, 0, 0) normal (1, 0, 0) x axis (0, 0, -1)
  line L1 (-114.55, 18) -> (-114.55, 5)
  line L2 (-120.75, 18) -> (-114.55, 18)
  line L3 (-120.75, 5) -> (-120.75, 18)
  line L4 (-114.55, 5) -> (-120.75, 5)
extrude "Extrude11" cut sketch "Open support-free clamp tool channel" along normal blind 8.2
position "Position1"
work_plane "WorkPlane68" AlongDistance -36.1 ExtraOffset 0
sketch "Remove above-rail flange" plane through (-36.1, 0, 0) normal (1, 0, 0) x axis (0, 0, -1)
  line L1 (-50, -75) -> (-50, -96)
  line L2 (-90, -75) -> (-50, -75)
  line L3 (-90, -96) -> (-90, -75)
  line L4 (-50, -96) -> (-90, -96)
extrude "Extrude68" cut sketch "Remove above-rail flange" along normal blind 12.2
work_plane "WorkPlane69" AlongDistance -36 ExtraOffset 0
sketch "Underside rail suspension arm" plane through (-36, 0, 0) normal (1, 0, 0) x axis (0, 0, -1)
  line L1 (-33, -75) -> (-33, -55)
  line L2 (-73, -75) -> (-33, -75)
  line L3 (-73, -95) -> (-73, -75)
  line L4 (-82, -95) -> (-73, -95)
  line L5 (-82, -65) -> (-82, -95)
  line L6 (-57, -55) -> (-82, -65)
  line L7 (-33, -55) -> (-57, -55)
work_plane "WorkPlane70" AlongDistance 72.9 ExtraOffset 0
sketch "Underside M5 clearance" plane through (0, 0, 72.9) normal (0, 0, 1) x axis (1, 0, 0)
  circle C1 centre (-30, -85) radius 2.7
work_plane "WorkPlane71" AlongDistance -36.1 ExtraOffset 0
sketch "Remove above-rail flange (1)" plane through (-36.1, 0, 0) normal (1, 0, 0) x axis (0, 0, -1)
  line L1 (-50, 96) -> (-50, 75)
  line L2 (-90, 96) -> (-50, 96)
  line L3 (-90, 75) -> (-90, 96)
  line L4 (-50, 75) -> (-90, 75)
extrude "Extrude71" cut sketch "Remove above-rail flange (1)" along normal blind 12.2
work_plane "WorkPlane72" AlongDistance -36 ExtraOffset 0
sketch "Underside rail suspension arm (1)" plane through (-36, 0, 0) normal (1, 0, 0) x axis (0, 0, -1)
  line L1 (-33, 75) -> (-33, 55)
  line L2 (-73, 75) -> (-33, 75)
  line L3 (-73, 95) -> (-73, 75)
  line L4 (-82, 95) -> (-73, 95)
  line L5 (-82, 65) -> (-82, 95)
  line L6 (-57, 55) -> (-82, 65)
  line L7 (-33, 55) -> (-57, 55)
work_plane "WorkPlane73" AlongDistance 72.9 ExtraOffset 0
sketch "Underside M5 clearance (1)" plane through (0, 0, 72.9) normal (0, 0, 1) x axis (1, 0, 0)
  circle C1 centre (-30, 85) radius 2.7
work_plane "WorkPlane72" AlongDistance 23.9 ExtraOffset 0
sketch "Remove above-rail flange" plane through (23.9, 0, 0) normal (1, 0, 0) x axis (0, 0, -1)
  line L1 (-50, -75) -> (-50, -96)
  line L2 (-90, -75) -> (-50, -75)
  line L3 (-90, -96) -> (-90, -75)
  line L4 (-50, -96) -> (-90, -96)
extrude "Extrude72" cut sketch "Remove above-rail flange" along normal blind 12.2
work_plane "WorkPlane73" AlongDistance 24 ExtraOffset 0
sketch "Underside rail suspension arm" plane through (24, 0, 0) normal (1, 0, 0) x axis (0, 0, -1)
  line L1 (-33, -75) -> (-33, -55)
  line L2 (-73, -75) -> (-33, -75)
  line L3 (-73, -95) -> (-73, -75)
  line L4 (-82, -95) -> (-73, -95)
  line L5 (-82, -65) -> (-82, -95)
  line L6 (-57, -55) -> (-82, -65)
  line L7 (-33, -55) -> (-57, -55)
work_plane "WorkPlane74" AlongDistance 72.9 ExtraOffset 0
sketch "Underside M5 clearance" plane through (0, 0, 72.9) normal (0, 0, 1) x axis (1, 0, 0)
  circle C1 centre (30, -85) radius 2.7
work_plane "WorkPlane75" AlongDistance 23.9 ExtraOffset 0
sketch "Remove above-rail flange (1)" plane through (23.9, 0, 0) normal (1, 0, 0) x axis (0, 0, -1)
  line L1 (-50, 96) -> (-50, 75)
  line L2 (-90, 96) -> (-50, 96)
  line L3 (-90, 75) -> (-90, 96)
  line L4 (-50, 75) -> (-90, 75)
extrude "Extrude75" cut sketch "Remove above-rail flange (1)" along normal blind 12.2
work_plane "WorkPlane76" AlongDistance 24 ExtraOffset 0
sketch "Underside rail suspension arm (1)" plane through (24, 0, 0) normal (1, 0, 0) x axis (0, 0, -1)
  line L1 (-33, 75) -> (-33, 55)
  line L2 (-73, 75) -> (-33, 75)
  line L3 (-73, 95) -> (-73, 75)
  line L4 (-82, 95) -> (-73, 95)
  line L5 (-82, 65) -> (-82, 95)
  line L6 (-57, 55) -> (-82, 65)
  line L7 (-33, 55) -> (-57, 55)
work_plane "WorkPlane77" AlongDistance 72.9 ExtraOffset 0
sketch "Underside M5 clearance (1)" plane through (0, 0, 72.9) normal (0, 0, 1) x axis (1, 0, 0)
  circle C1 centre (30, 85) radius 2.7
work_plane "WorkPlane78" AlongDistance 23.9 ExtraOffset 0
sketch "Remove upper sensor towers" plane through (23.9, 0, 0) normal (1, 0, 0) x axis (0, 0, -1)
  line L1 (-86.01, 24) -> (-86.01, -24)
  line L2 (-127, 24) -> (-86.01, 24)
  line L3 (-127, -24) -> (-127, 24)
  line L4 (-86.01, -24) -> (-127, -24)
extrude "Extrude78" cut sketch "Remove upper sensor towers" along normal blind 10.2
work_plane "WorkPlane79" AlongDistance 24 ExtraOffset 0
sketch "Lower sensor support" plane through (24, 0, 0) normal (1, 0, 0) x axis (0, 0, -1)
  line L1 (-4, -10) -> (-4, -23)
  line L2 (-35, -10) -> (-4, -10)
  line L3 (-35, -23) -> (-35, -10)
  line L4 (-4, -23) -> (-35, -23)
work_plane "WorkPlane80" AlongDistance 24 ExtraOffset 0
sketch "Lower sensor M3 insert" plane through (24, 0, 0) normal (1, 0, 0) x axis (0, 0, -1)
  circle C1 centre (-19.85, -16) radius 2
work_plane "WorkPlane81" AlongDistance 30.7 ExtraOffset 0
sketch "Lower sensor screw clearance" plane through (30.7, 0, 0) normal (1, 0, 0) x axis (0, 0, -1)
  circle C1 centre (-19.85, -16) radius 1.7
work_plane "WorkPlane82" AlongDistance 24 ExtraOffset 0
sketch "Lower sensor support (1)" plane through (24, 0, 0) normal (1, 0, 0) x axis (0, 0, -1)
  line L1 (-4, 23) -> (-4, 10)
  line L2 (-35, 23) -> (-4, 23)
  line L3 (-35, 10) -> (-35, 23)
  line L4 (-4, 10) -> (-35, 10)
work_plane "WorkPlane83" AlongDistance 24 ExtraOffset 0
sketch "Lower sensor M3 insert (1)" plane through (24, 0, 0) normal (1, 0, 0) x axis (0, 0, -1)
  circle C1 centre (-19.85, 16) radius 2
work_plane "WorkPlane84" AlongDistance 30.7 ExtraOffset 0
sketch "Lower sensor screw clearance (1)" plane through (30.7, 0, 0) normal (1, 0, 0) x axis (0, 0, -1)
  circle C1 centre (-19.85, 16) radius 1.7
work_plane "WorkPlane85" AlongDistance 23.9 ExtraOffset 0
sketch "Potentiometer body and lead clearance" plane through (23.9, 0, 0) normal (1, 0, 0) x axis (0, 0, -1)
  line L1 (-8.5, 8) -> (-8.5, -8)
  line L2 (-31.2, 8) -> (-8.5, 8)
  line L3 (-31.2, -8) -> (-31.2, 8)
  line L4 (-8.5, -8) -> (-31.2, -8)
work_plane "WorkPlane8" AlongDistance 40.4 ExtraOffset 0
sketch "Upper clamp split clear of lower mesh" plane through (40.4, 0, 0) normal (1, 0, 0) x axis (0, 0, -1)
  line L1 (-65, 0.2) -> (-65, -0.2)
  line L2 (-98, 0.2) -> (-65, 0.2)
  line L3 (-98, -0.2) -> (-98, 0.2)
  line L4 (-65, -0.2) -> (-98, -0.2)
extrude "Extrude8" cut sketch "Upper clamp split clear of lower mesh" along normal blind 8.2
work_plane "WorkPlane9" AlongDistance -8 ExtraOffset 0
sketch "Upper clamp insert" plane through (0, -8, 0) normal (0, 1, 0) x axis (1, 0, 0)
  circle C1 centre (44.5, -73) radius 2
extrude "Extrude9" cut sketch "Upper clamp insert" along normal blind 6.8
